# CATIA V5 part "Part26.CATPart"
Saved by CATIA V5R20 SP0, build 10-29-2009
Part number: 8PF0642WB-00-20130117_2
Revision: ANY
Definition: UNKNOWN
Nomenclature: 8PF0642WB-00-20130117_2
Source: Unknown
Bounding box of the stored display mesh (mm): x 1758.657 to 1958.657, y 1464.879 to 1471.765, z 0 to 6
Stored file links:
  C:\Users\Utente\Desktop\IO LAVORO\3D X SITO CF\CUMSA\3D files PF\PF 064200\Part26.CATPart
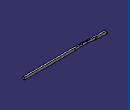
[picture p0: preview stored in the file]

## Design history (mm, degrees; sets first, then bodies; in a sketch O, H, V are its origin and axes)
Body1 "Cortar-Extruir1" (main body)
  Solid1: solid without history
